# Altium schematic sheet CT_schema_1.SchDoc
size 418 x 356 mm
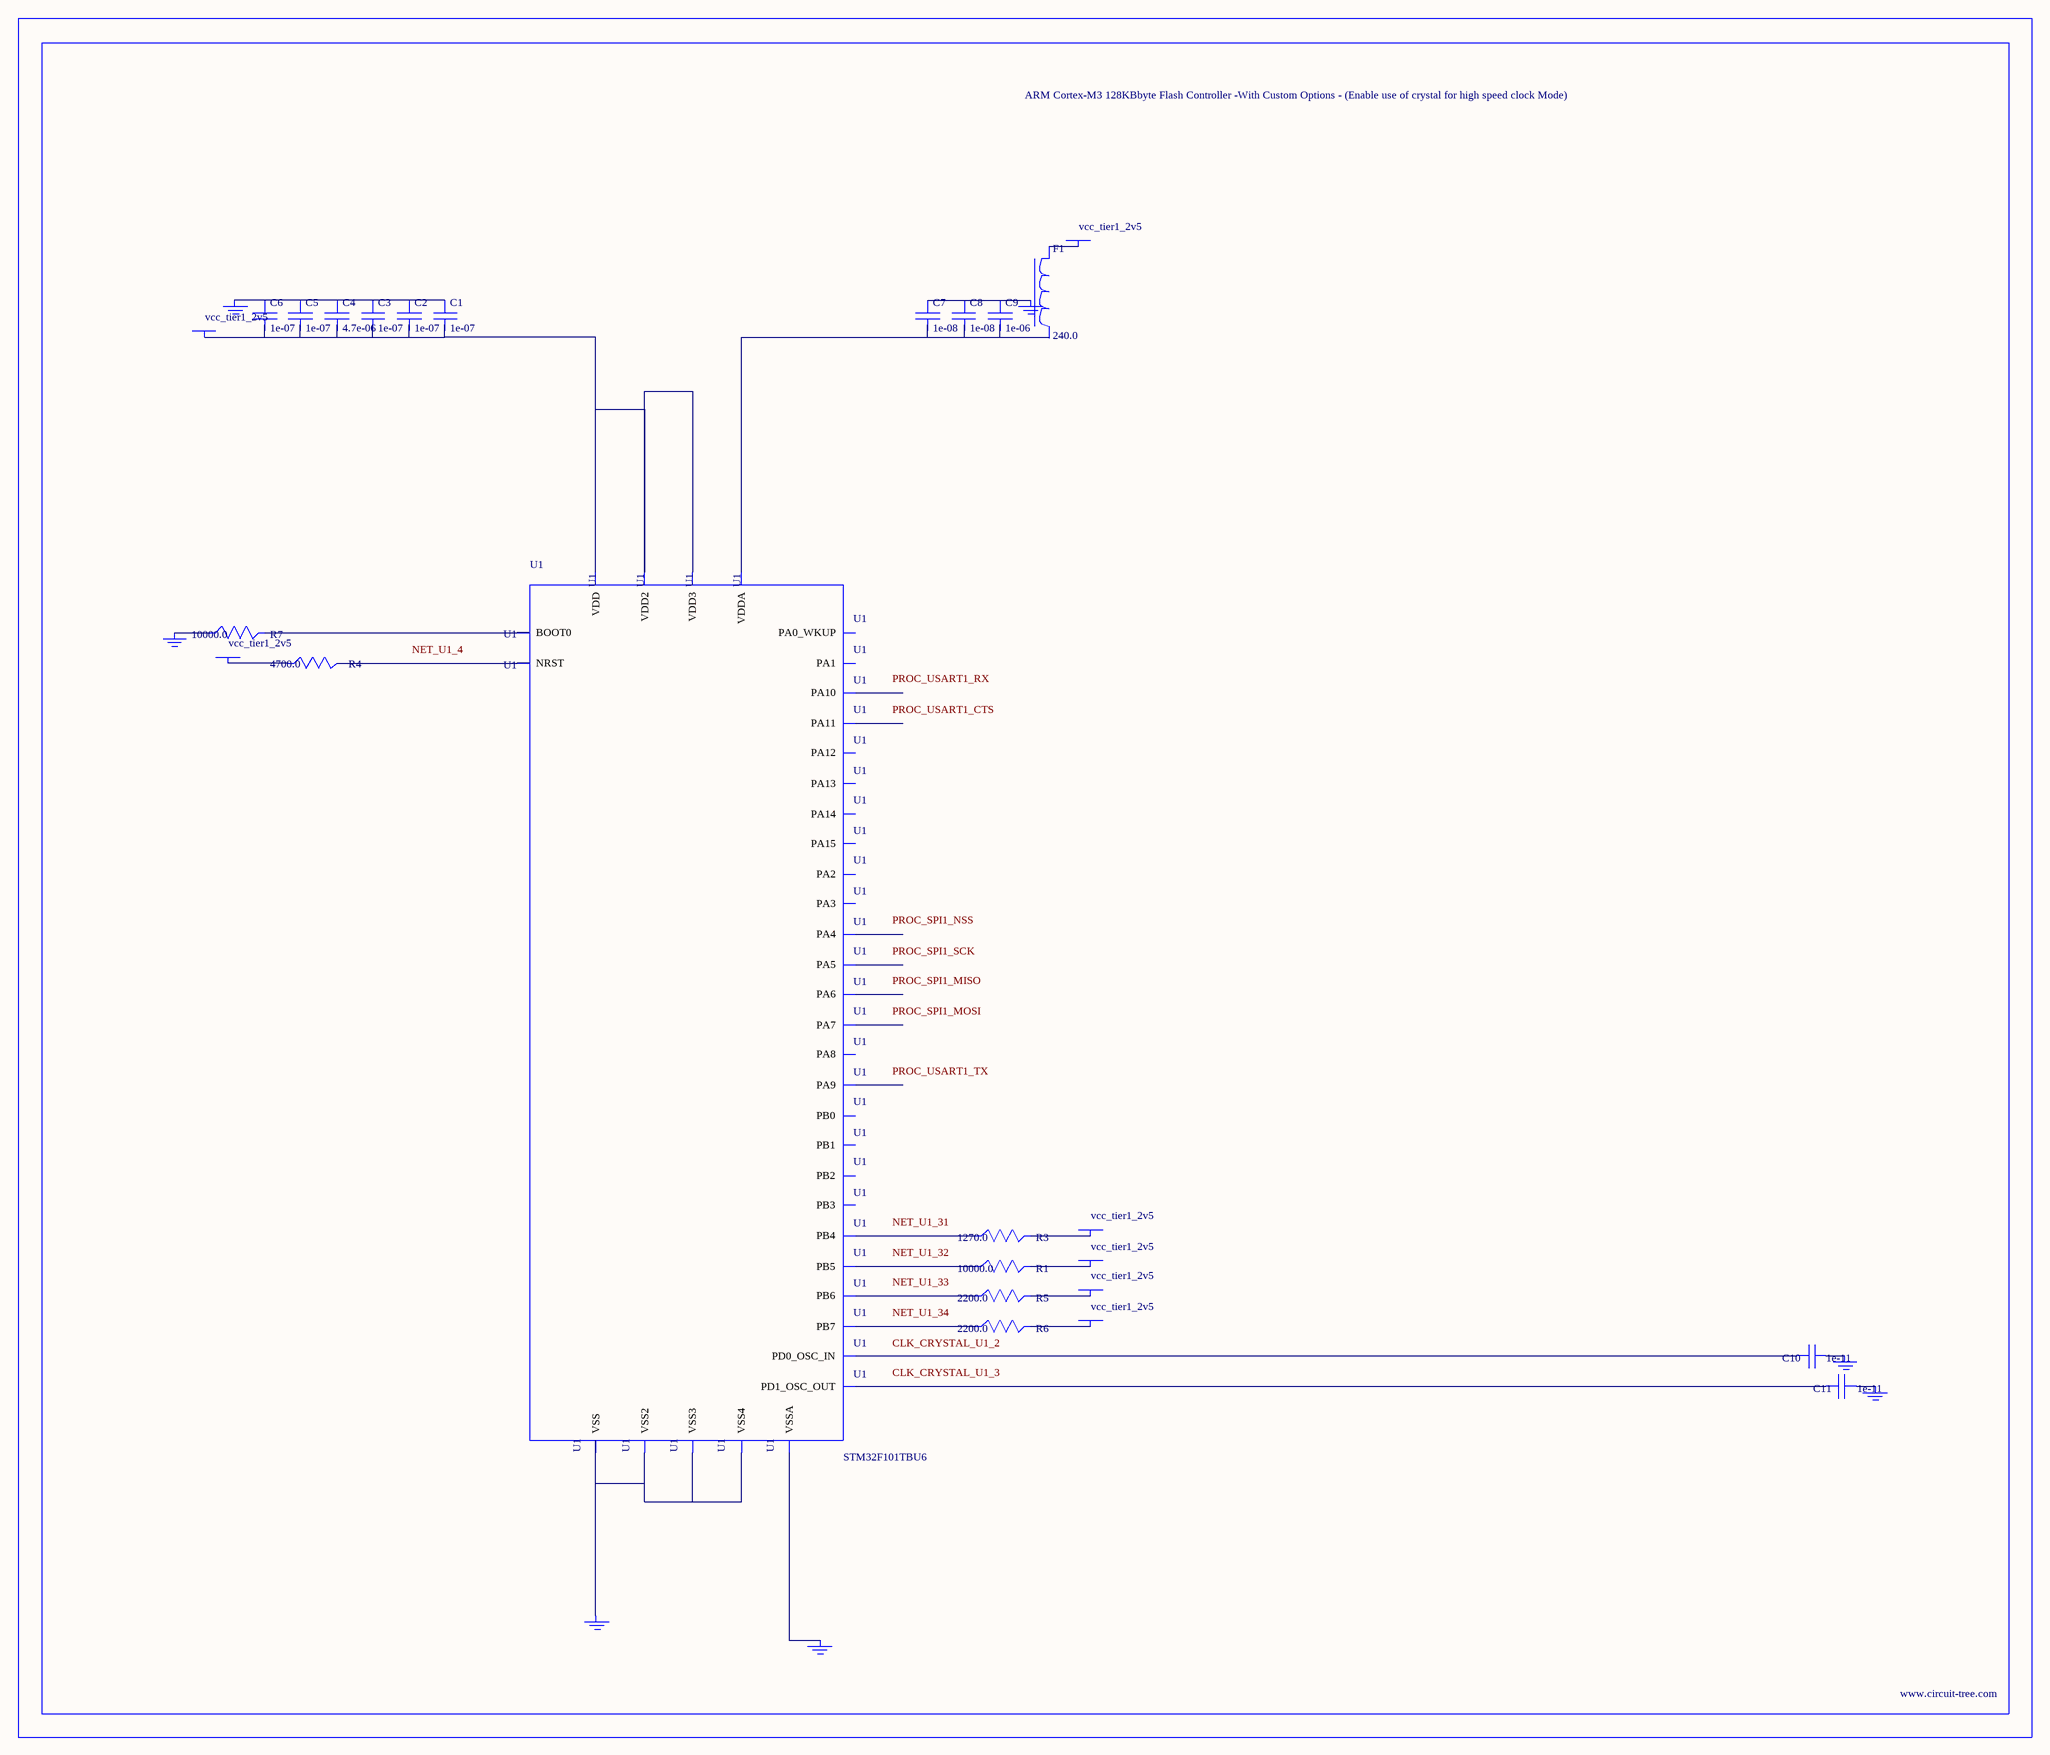
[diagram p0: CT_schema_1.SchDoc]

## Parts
BORDER0  (no value)
C1  1e-07  [C0603]
C2  1e-07  [C0603]
C3  1e-07  [C0603]
C4  4.7e-06  [C0603]
C5  1e-07  [C0603]
C6  1e-07  [C0603]
C7  1e-08  [C0603]
C8  1e-08  [C0603]
C9  1e-06  [C0603]
C10  1e-11  [C0402]
C11  1e-11  [C0402]
F1  240.0  [L0603]
GND_INSTANCE_0_0  (no value)
GND_INSTANCE_0_1  (no value)
GND_INSTANCE_0_2  (no value)
GND_INSTANCE_0_3  (no value)
GND_INSTANCE_0_4  (no value)
GND_INSTANCE_0_5  (no value)
GND_INSTANCE_0_6  (no value)
POWER_INSTANCE_0_0  vcc_tier1_2v5
POWER_INSTANCE_0_1  vcc_tier1_2v5
POWER_INSTANCE_0_2  vcc_tier1_2v5
POWER_INSTANCE_0_3  vcc_tier1_2v5
POWER_INSTANCE_0_4  vcc_tier1_2v5
POWER_INSTANCE_0_5  vcc_tier1_2v5
POWER_INSTANCE_0_6  vcc_tier1_2v5
R1  10000.0  [R0603]
R3  1270.0  [R0603]
R4  4700.0  [R0603]
R5  2200.0  [R0603]
R6  2200.0  [R0603]
R7  10000.0  [R0603]
U1  STM32F101TBU6  [VFQFPN36]

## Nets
NetC1_1: C1.1 C2.1 C3.1 C4.1 C5.1 C6.1 GND_INSTANCE_0_0.0(GND)
NetC1_2: C1.2 C2.2 C3.2 C4.2 C5.2 C6.2 POWER_INSTANCE_0_0.0(PWR) U1.1(VDD) U1.19(VDD2) U1.27(VDD3)
NetC7_1: C7.1 C8.1 C9.1 GND_INSTANCE_0_4.0(GND)
NetC7_2: C7.2 C8.2 C9.2 U1.6(VDDA)
NetC10_1: C10.1 GND_INSTANCE_0_1.0(GND)
NetC10_2: C10.2 U1.2(PD0_OSC_IN)
NetC11_1: C11.1 GND_INSTANCE_0_2.0(GND)
NetC11_2: C11.2 U1.3(PD1_OSC_OUT)
NetF1_1: F1.1 POWER_INSTANCE_0_1.0(PWR)
NetGND_INSTANCE_0_3_0: GND_INSTANCE_0_3.0(GND) U1.5(VSSA)
NetGND_INSTANCE_0_5_0: GND_INSTANCE_0_5.0(GND) R7.1
NetGND_INSTANCE_0_6_0: GND_INSTANCE_0_6.0(GND) U1.18(VSS) U1.26(VSS2) U1.36(VSS3) U1.37(VSS4)
NetPOWER_INSTANCE_0_2_0: POWER_INSTANCE_0_2.0(PWR) R4.1
NetPOWER_INSTANCE_0_3_0: POWER_INSTANCE_0_3.0(PWR) R3.2
NetPOWER_INSTANCE_0_4_0: POWER_INSTANCE_0_4.0(PWR) R1.2
NetPOWER_INSTANCE_0_5_0: POWER_INSTANCE_0_5.0(PWR) R5.2
NetPOWER_INSTANCE_0_6_0: POWER_INSTANCE_0_6.0(PWR) R6.2
NetR1_1: R1.1 U1.32(PB5)
NetR3_1: R3.1 U1.31(PB4)
NetR4_2: R4.2 U1.4(NRST)
NetR5_1: R5.1 U1.33(PB6)
NetR6_1: R6.1 U1.34(PB7)
NetR7_2: R7.2 U1.35(BOOT0)

Not connected (* = marked no-connect by the designer): F1 2; U1 7(PA0_WKUP) 8(PA1) 9(PA2) 10(PA3) 11(PA4) 12(PA5) 13(PA6) 14(PA7) 15(PB0) 16(PB1) 17(PB2) 20(PA8) 21(PA9) 22(PA10) 23(PA11) 24(PA12) 25(PA13) 28(PA14) 29(PA15) 30(PB3)

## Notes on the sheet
- Labels drawn without touching a wire or pin: CLK_CRYSTAL_U1_2, CLK_CRYSTAL_U1_3, NET_U1_4, NET_U1_31, NET_U1_32, NET_U1_33, NET_U1_34, PROC_SPI1_MISO, PROC_SPI1_MOSI, PROC_SPI1_NSS, PROC_SPI1_SCK, PROC_USART1_CTS, PROC_USART1_RX, PROC_USART1_TX

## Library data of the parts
BORDER0 = BORDER_PAGE0
C1-C3 C5 C6 = 06035C104K4Z2A
C4 = GRM188R6YA475KE15D
C7 C8 = 06035C103K4Z2A
C9 = C0603C105K3RACTU
C10 C11 = C0402C100K3GACTU
F1 = Z0603C241ASMST
GND_INSTANCE_0_0-GND_INSTANCE_0_6 = GND
POWER_INSTANCE_0_0-POWER_INSTANCE_0_6 = PWR
R1 R7 = RC0603JR-0710KL
R3 = RC0603FR-071K27L
R4 = RC0603JR-074K7L
R5 R6 = RC0603JR-072K2L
